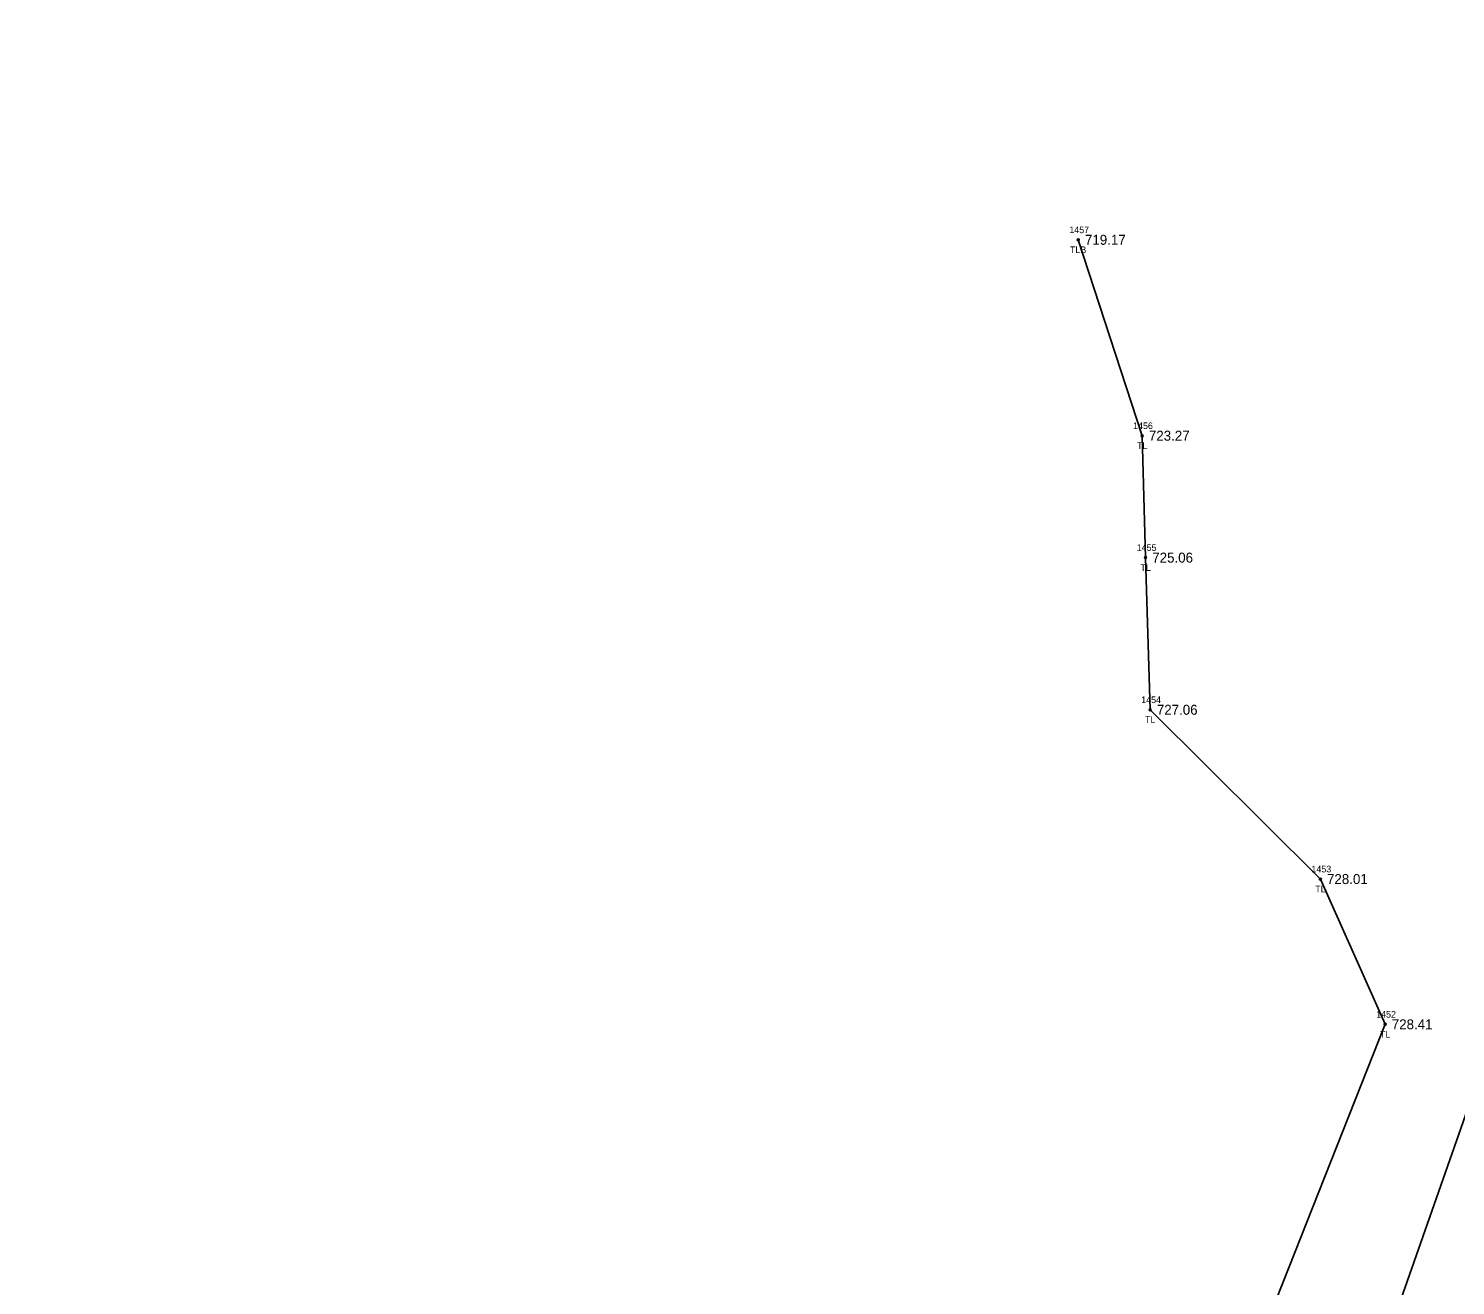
# Model space of a CAD drawing. Extents: x 1736563 to 1738032, y 1150548 to 1154248.
# Drawn here: x 1737107.2 to 1737322, y 1152422.1 to 1152611.4 of the extents above; entities that cross this region are included whole.
import ezdxf

# ---------------------------------------------------------------- set-up
doc = ezdxf.new("R2010")
doc.units = 0
for name, color, linetype in [('RD_EX_Road', 7, 'Continuous'), ('RD_EX_TX_VEG_ELEV', 7, 'Continuous'), ('RD_EX_VEG', 7, 'Continuous'), ('RD_EX_VEG_txCode', 7, 'Continuous'), ('RD_SMD_Locator', 7, 'Continuous')]:
    doc.layers.add(name, color=color, linetype=linetype)

msp = doc.modelspace()

# ---------------------------------------------------------------- linework, layer by layer
at = {"layer": 'RD_EX_Road'}
msp.add_lwpolyline([(1736868.01, 1151157.6), (1736882.54, 1151196.52), (1736892.4, 1151226.58), (1736911.77, 1151279.81), (1736926.32, 1151321.94), (1736959.92, 1151418.27), (1736977.6, 1151467.57), (1736993.86, 1151514.24), (1737026.63, 1151607.21), (1737059.17, 1151698.64), (1737091.53, 1151790.84), (1737119.9, 1151870.3), (1737125.51, 1151887.21), (1737129.74, 1151897.31), (1737157.61, 1151979.19), (1737191.07, 1152073.18), (1737224.57, 1152167.62), (1737258.08, 1152262.33), (1737292.51, 1152359.5), (1737326.83, 1152457.35), (1737361.84, 1152556.63), (1737380.81, 1152611.37), (1737392.07, 1152607.38)], dxfattribs=at)
at = {"layer": 'RD_EX_VEG'}
msp.add_lwpolyline([(1736959.7, 1151483.58), (1736969.15, 1151529.71), (1736993.52, 1151549.78), (1737013.17, 1151613.01), (1737045.07, 1151703.49), (1737071.59, 1151800.28), (1737137.09, 1151986), (1737166.47, 1152079.74), (1737210.3, 1152172.1), (1737243.02, 1152268.91), (1737273.26, 1152365.06), (1737311.38, 1152461.44), (1737301.63, 1152483.31), (1737276.02, 1152508.8), (1737275.33, 1152531.71), (1737274.82, 1152550.06), (1737265.2, 1152579.56)], dxfattribs=at)
at = {"layer": 'RD_SMD_Locator'}
for centre in [(1737265.2, 1152579.56), (1737274.82, 1152550.06), (1737275.33, 1152531.71), (1737276.02, 1152508.8), (1737301.63, 1152483.31), (1737311.38, 1152461.44)]:
    msp.add_circle(centre, 0.15, dxfattribs=at)

# ---------------------------------------------------------------- texts
at = {"layer": 'RD_EX_TX_VEG_ELEV'}
for s, p in [('719.17', (1737266.2, 1152578.81)), ('723.27', (1737275.82, 1152549.31)), ('725.06', (1737276.33, 1152530.96)), ('727.06', (1737277.02, 1152508.05)), ('728.01', (1737302.63, 1152482.56)), ('728.41', (1737312.38, 1152460.69))]:
    msp.add_text(s, height=1.5, dxfattribs=at).set_placement(p)
at = {"layer": 'RD_EX_VEG_txCode'}
for s, p in [('1457', (1737263.85, 1152580.56)), ('TLB', (1737263.95, 1152577.56)), ('1456', (1737273.45, 1152551.06)), ('TL', (1737274.05, 1152548.06)), ('1455', (1737273.99, 1152532.71)), ('TL', (1737274.56, 1152529.71)), ('1454', (1737274.67, 1152509.8)), ('TL', (1737275.24, 1152506.8)), ('1453', (1737300.29, 1152484.31)), ('TL', (1737300.86, 1152481.31)), ('1452', (1737310.03, 1152462.44)), ('TL', (1737310.61, 1152459.44))]:
    msp.add_text(s, height=1, dxfattribs=at).set_placement(p)

doc.saveas('drawing.dxf')
